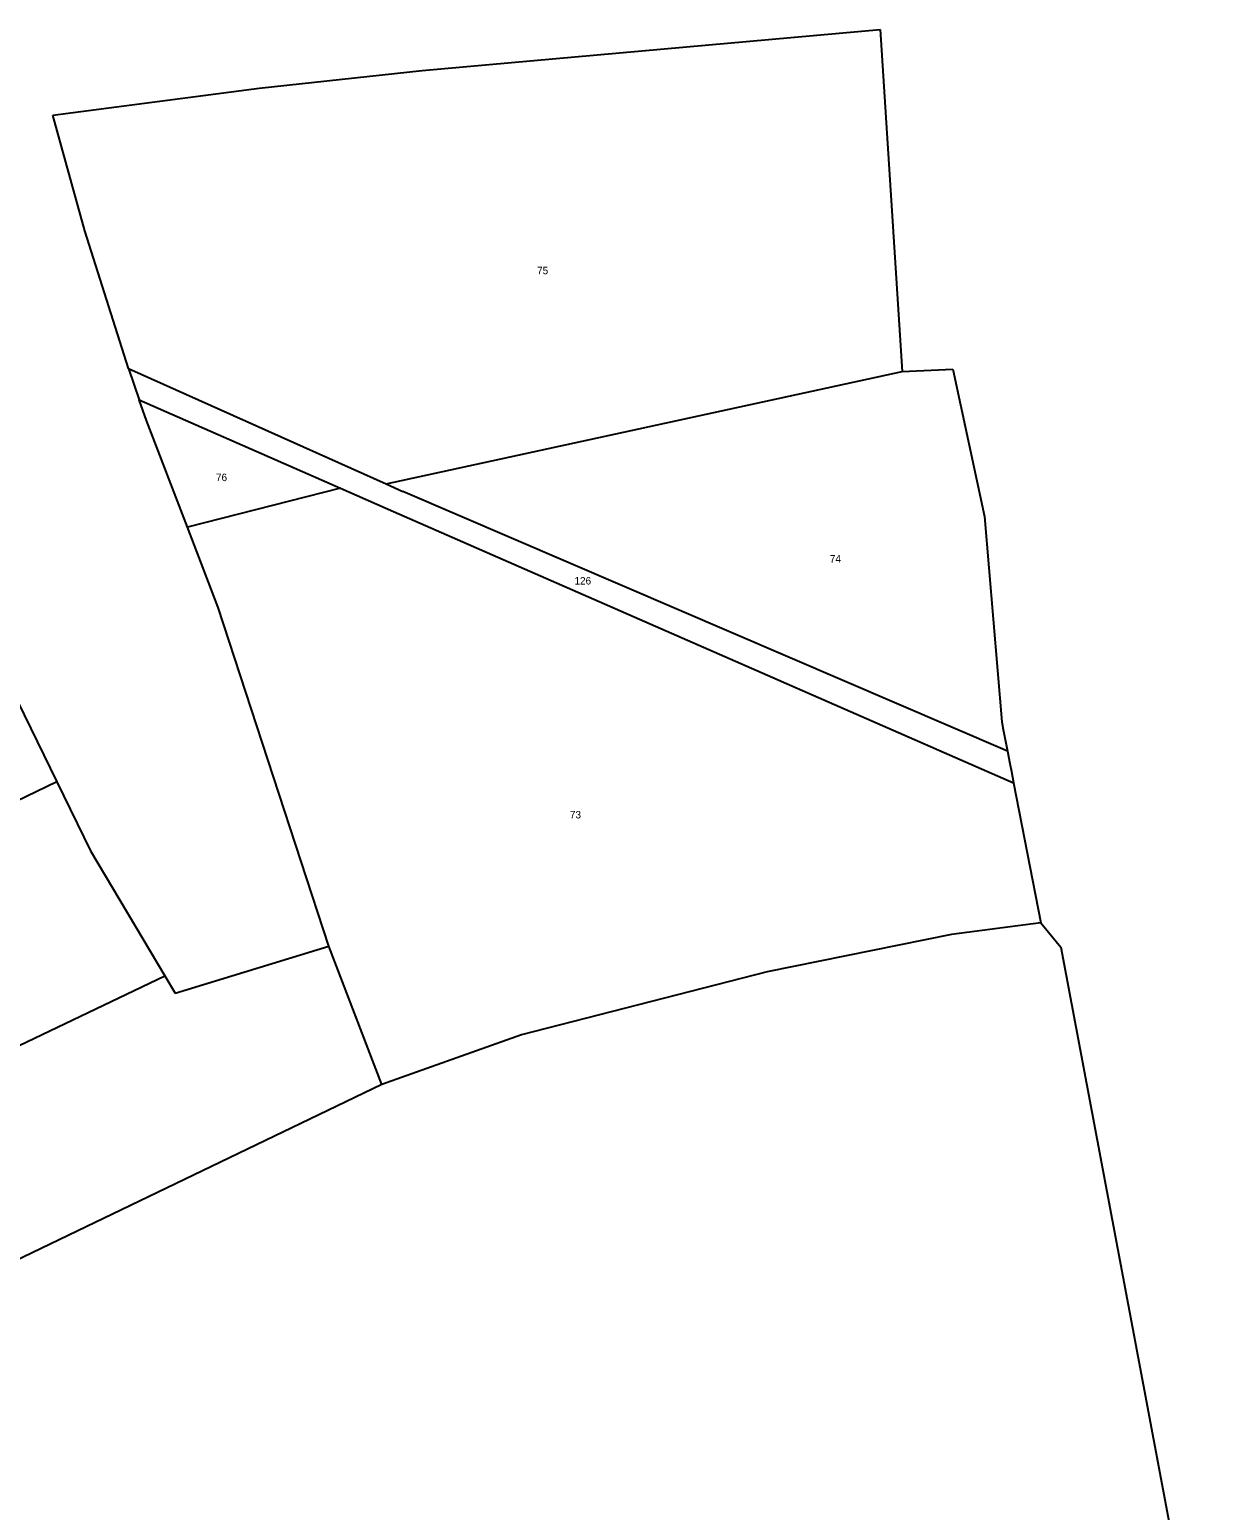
# Model space of a CAD drawing. Extents: x -752500 to -750336, y -1035826 to -1033500.
# Drawn here: x -750633.1 to -750361.2, y -1035440.1 to -1035103.4 of the extents above; entities that cross this region are included whole.
import ezdxf

# ---------------------------------------------------------------- set-up
doc = ezdxf.new("R2010")
doc.units = 0
for name, color, linetype in [('Hranice kat_území', 7, 'Continuous'), ('Hranice parcel', 7, 'Continuous'), ('Parcelní čísla', 7, 'Continuous')]:
    doc.layers.add(name, color=color, linetype=linetype)

msp = doc.modelspace()

# ---------------------------------------------------------------- linework, layer by layer
at = {"layer": 'Hranice kat_území'}
for p, q in [((-750543.82, -1035112.68), (-750439.65, -1035103.37)), ((-750439.65, -1035103.37), (-750434.66, -1035181.11)), ((-750580.87, -1035116.68), (-750543.82, -1035112.68)), ((-750627.75, -1035122.82), (-750580.87, -1035116.68)), ((-750620.53, -1035149.1), (-750627.75, -1035122.82)), ((-750610.6, -1035180.44), (-750620.53, -1035149.1)), ((-750610.6, -1035180.44), (-750608.12, -1035187.55)), ((-750434.66, -1035181.11), (-750423.17, -1035180.61)), ((-750423.17, -1035180.61), (-750415.94, -1035214.11)), ((-750606.45, -1035192.27), (-750608.12, -1035187.55)), ((-750597.18, -1035216.54), (-750606.45, -1035192.27)), ((-750590.21, -1035234.77), (-750597.18, -1035216.54)), ((-750415.94, -1035214.11), (-750412.04, -1035260.74)), ((-750565.07, -1035311.79), (-750590.21, -1035234.77)), ((-750640.28, -1035247.07), (-750626.88, -1035274.39)), ((-750412.04, -1035260.74), (-750411.69, -1035262.54)), ((-750411.69, -1035262.54), (-750410.73, -1035267.48)), ((-750410.73, -1035267.48), (-750410.19, -1035270.23)), ((-750410.19, -1035270.23), (-750409.84, -1035272.03)), ((-750409.84, -1035272.03), (-750409.34, -1035274.65)), ((-750626.88, -1035274.39), (-750619.19, -1035290.09)), ((-750409.34, -1035274.65), (-750403.15, -1035306.45)), ((-750619.19, -1035290.09), (-750602.3, -1035318.55)), ((-750403.15, -1035306.45), (-750398.6, -1035312.05)), ((-750599.98, -1035322.46), (-750565.07, -1035311.79)), ((-750398.6, -1035312.05), (-750379.9, -1035411.42)), ((-750602.3, -1035318.55), (-750599.98, -1035322.46)), ((-750379.9, -1035411.42), (-750361.2, -1035510.78))]:
    msp.add_line(p, q, dxfattribs=at)
at = {"layer": 'Hranice parcel'}
for p, q in [((-750610.6, -1035180.44), (-750551.99, -1035206.69)), ((-750551.99, -1035206.69), (-750434.66, -1035181.11)), ((-750608.12, -1035187.55), (-750562.36, -1035207.63)), ((-750562.36, -1035207.63), (-750597.18, -1035216.54)), ((-750562.36, -1035207.63), (-750550.34, -1035212.91)), ((-750551.99, -1035206.69), (-750548.24, -1035208.37)), ((-750410.73, -1035267.48), (-750548.24, -1035208.37)), ((-750550.34, -1035212.91), (-750409.34, -1035274.65)), ((-750626.88, -1035274.39), (-750788.73, -1035352.67)), ((-750403.15, -1035306.45), (-750423.47, -1035309.16)), ((-750423.47, -1035309.16), (-750465.41, -1035317.63)), ((-750553.02, -1035343.26), (-750565.07, -1035311.79)), ((-750465.41, -1035317.63), (-750521.26, -1035331.95)), ((-750761.16, -1035394.35), (-750602.3, -1035318.55)), ((-750521.26, -1035331.95), (-750553.02, -1035343.26)), ((-750553.02, -1035343.26), (-750737.45, -1035432.01))]:
    msp.add_line(p, q, dxfattribs=at)

# ---------------------------------------------------------------- texts
at = {"layer": 'Parcelní čísla'}
for s, p in [('75', (-750517.69, -1035159)), ('76', (-750590.69, -1035206.04)), ('74', (-750451.13, -1035224.55)), ('126', (-750509.19, -1035229.55)), ('73', (-750510.22, -1035282.74))]:
    msp.add_text(s, height=1.7, dxfattribs=at).set_placement(p)

doc.saveas('drawing.dxf')
